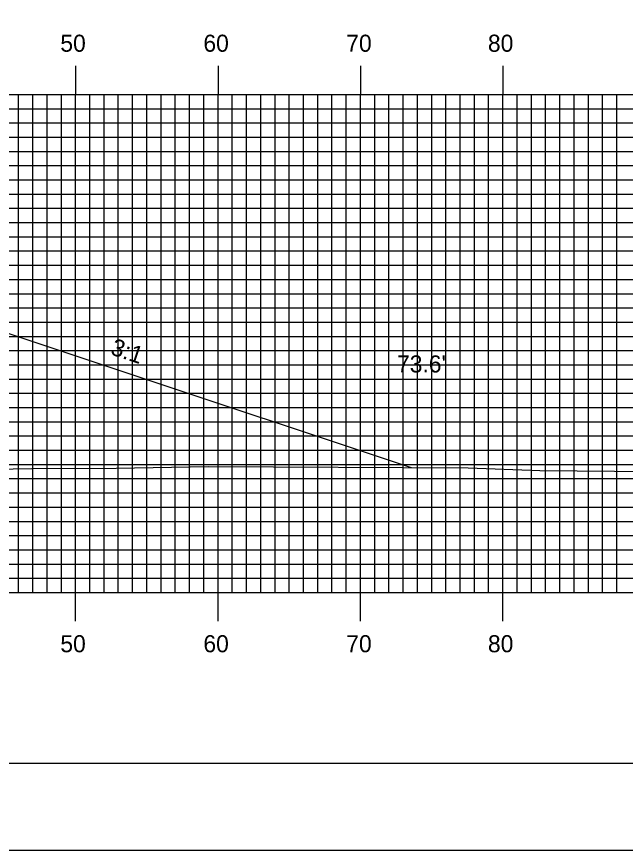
# Model space of a CAD drawing. Extents: x 1781467 to 1781810, y 442591 to 442811.
# Drawn here: x 1781678.3 to 1781721, y 442590.5 to 442649.1 of the extents above; entities that cross this region are included whole.
import ezdxf

# ---------------------------------------------------------------- set-up
doc = ezdxf.new("R2010")
doc.units = 0
for name, color, linetype in [('ANNOTATION', 7, 'Continuous'), ('BORDER', 7, 'Continuous'), ('D_Roadway_Centerline', 7, 'Continuous'), ('D_Roadway_SlopeLines', 7, 'Continuous'), ('D_Text_Standard', 7, 'Continuous'), ('H_V ANNOTATION', 7, 'Continuous'), ('MAJOR', 7, 'Continuous'), ('MINOR', 7, 'Continuous'), ('PLOT BOUNDARY', 7, 'Continuous'), ('S_Roadway_Centerline', 7, 'Continuous')]:
    doc.layers.add(name, color=color, linetype=linetype)

msp = doc.modelspace()

# ---------------------------------------------------------------- linework, layer by layer
at = {"layer": 'BORDER'}
msp.add_lwpolyline([(1781482.808, 442596.665), (1781802.808, 442596.665), (1781802.808, 442806.665), (1781482.808, 442806.665)], close=True, dxfattribs=at)
at = {"layer": 'D_Roadway_Centerline'}
msp.add_lwpolyline([(1781565.778, 442619.76), (1781600.408, 442631.303), (1781602.234, 442631.759), (1781612.408, 442634.303), (1781620.408, 442634.623), (1781632.408, 442634.863), (1781644.408, 442634.623), (1781652.408, 442634.303), (1781662.582, 442631.759), (1781664.408, 442631.303), (1781705.97, 442617.449)], dxfattribs=at)
at = {"layer": 'D_Roadway_SlopeLines'}
msp.add_lwpolyline([(1781652.408, 442634.303), (1781664.408, 442631.303), (1781705.97, 442617.449)], dxfattribs=at)
at = {"layer": 'MAJOR'}
for p, q in [((1781682.408, 442645.669), (1781682.408, 442643.665)), ((1781692.408, 442645.669), (1781692.408, 442643.665)), ((1781702.408, 442645.669), (1781702.408, 442643.665)), ((1781712.408, 442645.669), (1781712.408, 442643.665)), ((1781492.408, 442643.665), (1781772.408, 442643.665)), ((1781492.408, 442643.665), (1781772.408, 442643.665)), ((1781682.408, 442608.665), (1781682.408, 442643.665)), ((1781692.408, 442608.665), (1781692.408, 442643.665)), ((1781702.408, 442608.665), (1781702.408, 442643.665)), ((1781712.408, 442608.665), (1781712.408, 442643.665)), ((1781492.408, 442638.665), (1781772.408, 442638.665)), ((1781492.408, 442633.665), (1781772.408, 442633.665)), ((1781492.408, 442628.665), (1781772.408, 442628.665)), ((1781492.408, 442623.665), (1781772.408, 442623.665)), ((1781492.408, 442618.665), (1781772.408, 442618.665)), ((1781492.408, 442613.665), (1781772.408, 442613.665)), ((1781492.408, 442608.665), (1781772.408, 442608.665)), ((1781492.408, 442608.665), (1781772.408, 442608.665)), ((1781682.408, 442606.661), (1781682.408, 442608.665)), ((1781692.408, 442606.661), (1781692.408, 442608.665)), ((1781702.408, 442606.661), (1781702.408, 442608.665)), ((1781712.408, 442606.661), (1781712.408, 442608.665))]:
    msp.add_line(p, q, dxfattribs=at)
at = {"layer": 'MINOR'}
for p, q in [((1781678.408, 442608.665), (1781678.408, 442643.665)), ((1781679.408, 442608.665), (1781679.408, 442643.665)), ((1781680.408, 442608.665), (1781680.408, 442643.665)), ((1781681.408, 442608.665), (1781681.408, 442643.665)), ((1781683.408, 442608.665), (1781683.408, 442643.665)), ((1781684.408, 442608.665), (1781684.408, 442643.665)), ((1781685.408, 442608.665), (1781685.408, 442643.665)), ((1781686.408, 442608.665), (1781686.408, 442643.665)), ((1781687.408, 442608.665), (1781687.408, 442643.665)), ((1781688.408, 442608.665), (1781688.408, 442643.665)), ((1781689.408, 442608.665), (1781689.408, 442643.665)), ((1781690.408, 442608.665), (1781690.408, 442643.665)), ((1781691.408, 442608.665), (1781691.408, 442643.665)), ((1781693.408, 442608.665), (1781693.408, 442643.665)), ((1781694.408, 442608.665), (1781694.408, 442643.665)), ((1781695.408, 442608.665), (1781695.408, 442643.665)), ((1781696.408, 442608.665), (1781696.408, 442643.665)), ((1781697.408, 442608.665), (1781697.408, 442643.665)), ((1781698.408, 442608.665), (1781698.408, 442643.665)), ((1781699.408, 442608.665), (1781699.408, 442643.665)), ((1781700.408, 442608.665), (1781700.408, 442643.665)), ((1781701.408, 442608.665), (1781701.408, 442643.665)), ((1781703.408, 442608.665), (1781703.408, 442643.665)), ((1781704.408, 442608.665), (1781704.408, 442643.665)), ((1781705.408, 442608.665), (1781705.408, 442643.665)), ((1781706.408, 442608.665), (1781706.408, 442643.665)), ((1781707.408, 442608.665), (1781707.408, 442643.665)), ((1781708.408, 442608.665), (1781708.408, 442643.665)), ((1781709.408, 442608.665), (1781709.408, 442643.665)), ((1781710.408, 442608.665), (1781710.408, 442643.665)), ((1781711.408, 442608.665), (1781711.408, 442643.665)), ((1781713.408, 442608.665), (1781713.408, 442643.665)), ((1781714.408, 442608.665), (1781714.408, 442643.665)), ((1781715.408, 442608.665), (1781715.408, 442643.665)), ((1781716.408, 442608.665), (1781716.408, 442643.665)), ((1781717.408, 442608.665), (1781717.408, 442643.665)), ((1781718.408, 442608.665), (1781718.408, 442643.665)), ((1781719.408, 442608.665), (1781719.408, 442643.665)), ((1781720.408, 442608.665), (1781720.408, 442643.665)), ((1781492.408, 442642.665), (1781772.408, 442642.665)), ((1781492.408, 442641.665), (1781772.408, 442641.665)), ((1781492.408, 442640.665), (1781772.408, 442640.665)), ((1781492.408, 442639.665), (1781772.408, 442639.665)), ((1781492.408, 442637.665), (1781772.408, 442637.665)), ((1781492.408, 442636.665), (1781772.408, 442636.665)), ((1781492.408, 442635.665), (1781772.408, 442635.665)), ((1781492.408, 442634.665), (1781772.408, 442634.665)), ((1781492.408, 442632.665), (1781772.408, 442632.665)), ((1781492.408, 442631.665), (1781772.408, 442631.665)), ((1781492.408, 442630.665), (1781772.408, 442630.665)), ((1781492.408, 442629.665), (1781772.408, 442629.665)), ((1781492.408, 442627.665), (1781772.408, 442627.665)), ((1781492.408, 442626.665), (1781772.408, 442626.665)), ((1781492.408, 442625.665), (1781772.408, 442625.665)), ((1781492.408, 442624.665), (1781772.408, 442624.665)), ((1781492.408, 442622.665), (1781772.408, 442622.665)), ((1781492.408, 442621.665), (1781772.408, 442621.665)), ((1781492.408, 442620.665), (1781772.408, 442620.665)), ((1781492.408, 442619.665), (1781772.408, 442619.665)), ((1781492.408, 442617.665), (1781772.408, 442617.665)), ((1781492.408, 442616.665), (1781772.408, 442616.665)), ((1781492.408, 442615.665), (1781772.408, 442615.665)), ((1781492.408, 442614.665), (1781772.408, 442614.665)), ((1781492.408, 442612.665), (1781772.408, 442612.665)), ((1781492.408, 442611.665), (1781772.408, 442611.665)), ((1781492.408, 442610.665), (1781772.408, 442610.665)), ((1781492.408, 442609.665), (1781772.408, 442609.665))]:
    msp.add_line(p, q, dxfattribs=at)
at = {"layer": 'PLOT BOUNDARY'}
msp.add_lwpolyline([(1781466.621, 442590.547), (1781806.621, 442590.547), (1781806.621, 442810.547), (1781466.621, 442810.547)], close=True, dxfattribs=at)
at = {"layer": 'S_Roadway_Centerline'}
msp.add_lwpolyline([(1781593.567, 442618.68), (1781608.597, 442618.177), (1781616.719, 442617.808), (1781624.496, 442617.741), (1781631.649, 442617.618), (1781646.065, 442617.448), (1781651.082, 442617.458), (1781656.082, 442617.435), (1781674.097, 442617.286), (1781679.323, 442617.384), (1781685.257, 442617.402), (1781691.748, 442617.527), (1781709.961, 442617.427), (1781714.991, 442617.25), (1781722.855, 442617.175), (1781728.07, 442617.319), (1781744.401, 442617.437), (1781750.717, 442617.316), (1781760.762, 442617.614), (1781772.408, 442617.524)], dxfattribs=at)

# ---------------------------------------------------------------- texts
at = {"layer": 'ANNOTATION'}
msp.add_text('3:1', height=1.2, rotation=341.56522, dxfattribs=at).set_placement((1781684.792, 442625.416))
at = {"layer": 'D_Text_Standard'}
msp.add_text("73.6'", height=1.2, dxfattribs=at).set_placement((1781704.976, 442624.127))
at = {"layer": 'H_V ANNOTATION'}
for s, p in [('50', (1781681.337, 442646.665)), ('60', (1781691.38, 442646.665)), ('70', (1781701.412, 442646.665)), ('80', (1781711.359, 442646.665)), ('50', (1781681.337, 442604.465)), ('60', (1781691.38, 442604.465)), ('70', (1781701.412, 442604.465)), ('80', (1781711.359, 442604.465))]:
    msp.add_text(s, height=1.2, dxfattribs=at).set_placement(p)

doc.saveas('drawing.dxf')
